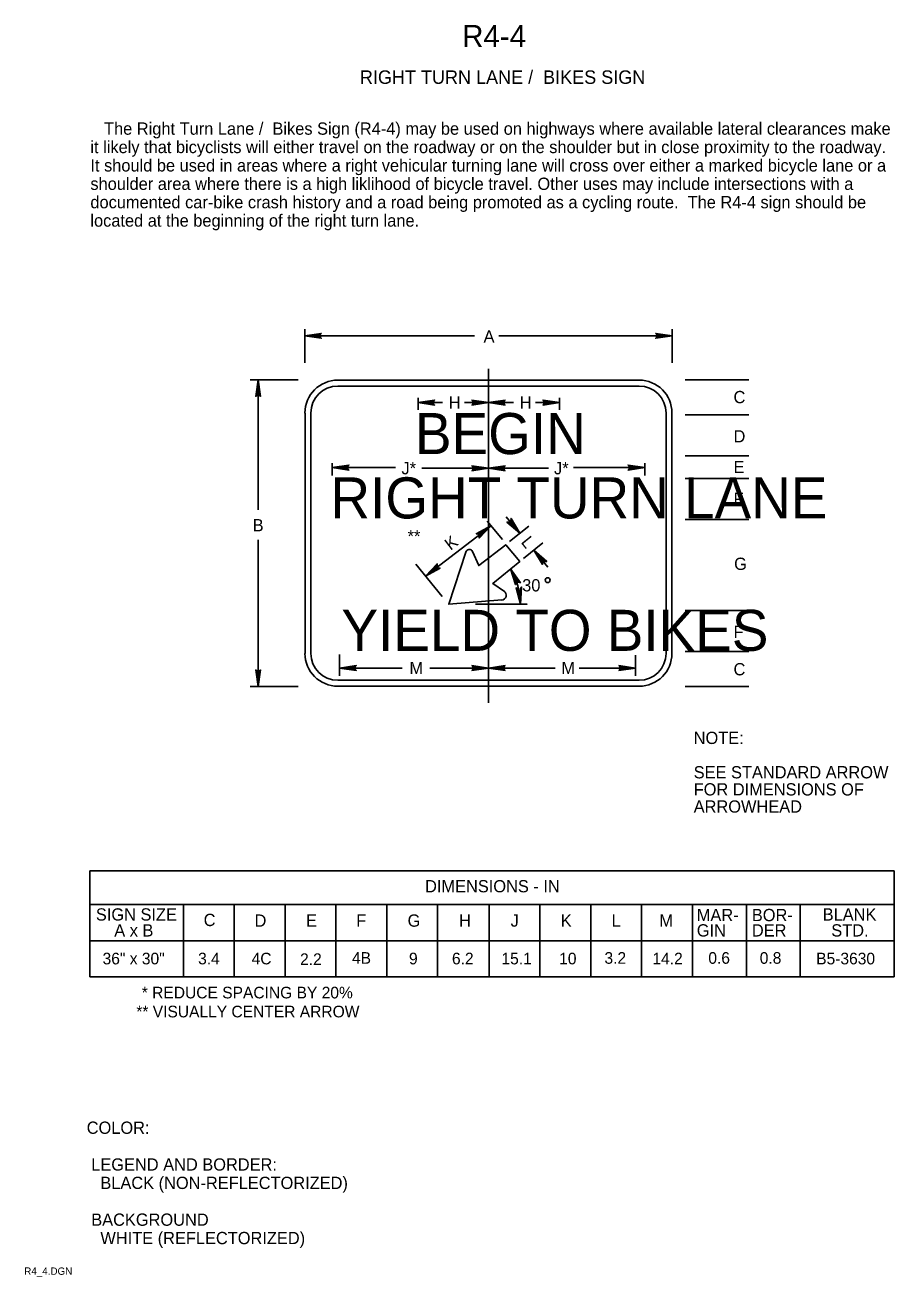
# Model space of a CAD drawing. Extents: x 0.013 to 0.19, y 0.004 to 0.259.
import ezdxf

# ---------------------------------------------------------------- set-up
doc = ezdxf.new("R2010")
doc.units = 0
for name, color, linetype in [('1', 7, 'Continuous'), ('2', 7, 'Continuous'), ('3', 7, 'Continuous'), ('7', 7, 'Continuous')]:
    doc.layers.add(name, color=color, linetype=linetype)

msp = doc.modelspace()

# ---------------------------------------------------------------- linework, layer by layer
at = {"layer": '1'}
for p, q in [((0.06963, 0.19038), (0.06963, 0.19725)), ((0.14463, 0.19038), (0.14463, 0.19725)), ((0.10425, 0.19587), (0.06963, 0.19587)), ((0.14463, 0.19587), (0.10925, 0.19587)), ((0.10712, 0.18913), (0.10712, 0.12102)), ((0.06825, 0.18688), (0.0585, 0.18688)), ((0.06012, 0.16037), (0.06012, 0.18688)), ((0.07637, 0.18682), (0.13787, 0.18682)), ((0.16025, 0.18688), (0.14725, 0.18688)), ((0.09275, 0.18075), (0.09275, 0.18325)), ((0.09775, 0.18225), (0.09275, 0.18225)), ((0.10712, 0.18225), (0.10225, 0.18225)), ((0.11225, 0.18225), (0.10712, 0.18225)), ((0.12162, 0.18225), (0.11675, 0.18225)), ((0.12162, 0.18075), (0.12162, 0.18325)), ((0.06968, 0.13112), (0.06968, 0.18013)), ((0.14457, 0.18013), (0.14457, 0.13112)), ((0.16025, 0.17975), (0.14725, 0.17975)), ((0.16025, 0.17137), (0.14725, 0.17137)), ((0.07525, 0.16737), (0.07525, 0.16987)), ((0.08812, 0.169), (0.07525, 0.169)), ((0.10712, 0.16887), (0.0935, 0.16887)), ((0.11938, 0.16887), (0.10712, 0.16887)), ((0.139, 0.169), (0.1245, 0.169)), ((0.139, 0.16737), (0.139, 0.16987)), ((0.16025, 0.16675), (0.14725, 0.16675)), ((0.11353, 0.15558), (0.11075, 0.15894)), ((0.16025, 0.15838), (0.14725, 0.15838)), ((0.09425, 0.14688), (0.10767, 0.15714)), ((0.10688, 0.15809), (0.11001, 0.15434)), ((0.11143, 0.15391), (0.11538, 0.15705)), ((0.06012, 0.12437), (0.06012, 0.15425)), ((0.11427, 0.15049), (0.11822, 0.15363)), ((0.11921, 0.14867), (0.11635, 0.15215)), ((0.09766, 0.1427), (0.09229, 0.14928)), ((0.115, 0.14113), (0.1045, 0.14113)), ((0.16025, 0.13987), (0.14725, 0.13987)), ((0.07675, 0.1265), (0.07675, 0.13087)), ((0.13712, 0.13075), (0.13712, 0.1265)), ((0.16025, 0.1315), (0.14725, 0.1315)), ((0.0895, 0.12812), (0.07675, 0.12812)), ((0.10712, 0.12812), (0.09513, 0.12812)), ((0.12075, 0.12812), (0.10712, 0.12812)), ((0.13712, 0.12812), (0.12563, 0.12812)), ((0.06825, 0.12437), (0.0585, 0.12437)), ((0.13787, 0.12443), (0.07637, 0.12443)), ((0.16025, 0.12437), (0.14725, 0.12437))]:
    msp.add_line(p, q, dxfattribs=at)
for points in [[(0.07287, 0.1955), (0.07275, 0.19575), (0.06963, 0.19587), (0.07287, 0.1955), (0.073, 0.19537), (0.06963, 0.19587), (0.07275, 0.196), (0.07287, 0.19625), (0.06963, 0.19587), (0.073, 0.19637), (0.07287, 0.19625)], [(0.14138, 0.19625), (0.1415, 0.196), (0.14463, 0.19587), (0.14138, 0.19625), (0.14125, 0.19637), (0.14463, 0.19587), (0.1415, 0.19575), (0.14138, 0.1955), (0.14463, 0.19587), (0.14125, 0.19537), (0.14138, 0.1955)], [(0.05975, 0.18363), (0.06, 0.18375), (0.06012, 0.18688), (0.05975, 0.18363), (0.05963, 0.1835), (0.06012, 0.18688), (0.06025, 0.18375), (0.0605, 0.18363), (0.06012, 0.18688), (0.06062, 0.1835), (0.0605, 0.18363)], [(0.096, 0.18188), (0.09588, 0.18213), (0.09275, 0.18225), (0.096, 0.18188), (0.09613, 0.18175), (0.09275, 0.18225), (0.09588, 0.18238), (0.096, 0.18263), (0.09275, 0.18225), (0.09613, 0.18275), (0.096, 0.18263)], [(0.10388, 0.18263), (0.104, 0.18238), (0.10712, 0.18225), (0.10388, 0.18263), (0.10375, 0.18275), (0.10712, 0.18225), (0.104, 0.18213), (0.10388, 0.18188), (0.10712, 0.18225), (0.10375, 0.18175), (0.10388, 0.18188)], [(0.11038, 0.18188), (0.11025, 0.18213), (0.10712, 0.18225), (0.11038, 0.18188), (0.1105, 0.18175), (0.10712, 0.18225), (0.11025, 0.18238), (0.11038, 0.18263), (0.10712, 0.18225), (0.1105, 0.18275), (0.11038, 0.18263)], [(0.11838, 0.18263), (0.1185, 0.18238), (0.12162, 0.18225), (0.11838, 0.18263), (0.11825, 0.18275), (0.12162, 0.18225), (0.1185, 0.18213), (0.11838, 0.18188), (0.12162, 0.18225), (0.11825, 0.18175), (0.11838, 0.18188)], [(0.0785, 0.16862), (0.07838, 0.16887), (0.07525, 0.169), (0.0785, 0.16862), (0.07863, 0.1685), (0.07525, 0.169), (0.07838, 0.16912), (0.0785, 0.16937), (0.07525, 0.169), (0.07863, 0.1695), (0.0785, 0.16937)], [(0.10388, 0.16925), (0.104, 0.169), (0.10712, 0.16887), (0.10388, 0.16925), (0.10375, 0.16937), (0.10712, 0.16887), (0.104, 0.16875), (0.10388, 0.1685), (0.10712, 0.16887), (0.10375, 0.16837), (0.10388, 0.1685)], [(0.11038, 0.1685), (0.11025, 0.16875), (0.10712, 0.16887), (0.11038, 0.1685), (0.1105, 0.16837), (0.10712, 0.16887), (0.11025, 0.169), (0.11038, 0.16925), (0.10712, 0.16887), (0.1105, 0.16937), (0.11038, 0.16925)], [(0.13575, 0.16937), (0.13587, 0.16912), (0.139, 0.169), (0.13575, 0.16937), (0.13562, 0.1695), (0.139, 0.169), (0.13587, 0.16887), (0.13575, 0.16862), (0.139, 0.169), (0.13562, 0.1685), (0.13575, 0.16862)], [(0.11175, 0.15838), (0.11163, 0.15825), (0.1135, 0.15563), (0.11175, 0.15838), (0.11175, 0.15863), (0.1135, 0.15563), (0.11138, 0.15788), (0.11113, 0.15788), (0.1135, 0.15563), (0.11088, 0.15788), (0.11113, 0.15788)], [(0.10487, 0.1555), (0.105, 0.15538), (0.10762, 0.15713), (0.10487, 0.1555), (0.10462, 0.1555), (0.10762, 0.15713), (0.10525, 0.15513), (0.10525, 0.15488), (0.10762, 0.15713), (0.10525, 0.15463), (0.10525, 0.15488)], [(0.11038, 0.14375), (0.108, 0.14538), (0.1135, 0.14988), (0.11063, 0.15325), (0.10512, 0.149), (0.10388, 0.15188), (0.10388, 0.15188)], [(0.1025, 0.15175), (0.099, 0.14113), (0.10988, 0.142)], [(0.11813, 0.1495), (0.11825, 0.14963), (0.11638, 0.15213), (0.11813, 0.1495), (0.11813, 0.14925), (0.11638, 0.15213), (0.1185, 0.14988), (0.11875, 0.14988), (0.11638, 0.15213), (0.119, 0.14988), (0.11875, 0.14988)], [(0.097, 0.1485), (0.09688, 0.14863), (0.09425, 0.14688), (0.097, 0.1485), (0.09725, 0.1485), (0.09425, 0.14688), (0.09663, 0.14888), (0.09663, 0.14913), (0.09425, 0.14688), (0.09663, 0.14938), (0.09663, 0.14913)], [(0.11275, 0.14538), (0.11288, 0.1455), (0.11163, 0.14838), (0.11275, 0.14538), (0.11263, 0.14513), (0.11163, 0.14838), (0.11313, 0.14563), (0.11338, 0.14563), (0.11163, 0.14838), (0.11363, 0.1455), (0.11338, 0.14563)], [(0.11375, 0.14438), (0.11363, 0.14438), (0.11363, 0.14113), (0.11375, 0.14438), (0.11388, 0.14463), (0.11363, 0.14113), (0.11313, 0.14413), (0.113, 0.14438), (0.11363, 0.14113), (0.11275, 0.1445), (0.113, 0.14438)], [(0.0605, 0.12763), (0.06025, 0.1275), (0.06012, 0.12437), (0.0605, 0.12763), (0.06062, 0.12775), (0.06012, 0.12437), (0.06, 0.1275), (0.05975, 0.12763), (0.06012, 0.12437), (0.05963, 0.12775), (0.05975, 0.12763)], [(0.08, 0.12775), (0.07988, 0.128), (0.07675, 0.12812), (0.08, 0.12775), (0.08013, 0.12763), (0.07675, 0.12812), (0.07988, 0.12825), (0.08, 0.1285), (0.07675, 0.12812), (0.08013, 0.12862), (0.08, 0.1285)], [(0.10388, 0.1285), (0.104, 0.12825), (0.10712, 0.12812), (0.10388, 0.1285), (0.10375, 0.12862), (0.10712, 0.12812), (0.104, 0.128), (0.10388, 0.12775), (0.10712, 0.12812), (0.10375, 0.12763), (0.10388, 0.12775)], [(0.11038, 0.12775), (0.11025, 0.128), (0.10712, 0.12812), (0.11038, 0.12775), (0.1105, 0.12763), (0.10712, 0.12812), (0.11025, 0.12825), (0.11038, 0.1285), (0.10712, 0.12812), (0.1105, 0.12862), (0.11038, 0.1285)], [(0.13387, 0.1285), (0.134, 0.12825), (0.13712, 0.12812), (0.13387, 0.1285), (0.13375, 0.12862), (0.13712, 0.12812), (0.134, 0.128), (0.13387, 0.12775), (0.13712, 0.12812), (0.13375, 0.12763), (0.13387, 0.12775)]]:
    msp.add_lwpolyline(points, dxfattribs=at)
msp.add_circle((0.11919, 0.14604), 0.0005, dxfattribs=at)
for centre, radius, start, end in [((0.07637, 0.18013), 0.0067, 90, 180), ((0.13787, 0.18013), 0.0067, 0, 90), ((0.10321, 0.15154), 0.000749, 26.7363, 165.3694), ((0.09907, 0.14104), 0.01455, 0.41, 30.1116), ((0.10975, 0.14299), 0.001, 274.205, 54.7468), ((0.07637, 0.13112), 0.0067, 180, 270), ((0.13787, 0.13112), 0.0067, 270, 0)]:
    msp.add_arc(centre, radius, start, end, dxfattribs=at)
msp.add_ellipse((0.09898, 0.14108), major_axis=(0, -0.0161), ratio=0.99998, start_param=1.5707963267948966, end_param=1.5707963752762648, dxfattribs=at)
at = {"layer": '3'}
for p, q in [((0.07637, 0.18563), (0.13787, 0.18563)), ((0.07088, 0.13112), (0.07088, 0.18013)), ((0.14338, 0.18013), (0.14338, 0.13112)), ((0.13787, 0.12563), (0.07637, 0.12563)), ((0.02575, 0.08675), (0.18988, 0.08675)), ((0.02575, 0.08675), (0.02575, 0.06513)), ((0.18988, 0.08675), (0.18988, 0.06513)), ((0.18988, 0.07988), (0.02575, 0.07988)), ((0.04487, 0.07988), (0.04487, 0.06513)), ((0.05525, 0.07988), (0.05525, 0.06513)), ((0.06563, 0.07988), (0.06563, 0.06513)), ((0.076, 0.07988), (0.076, 0.06513)), ((0.08638, 0.07988), (0.08638, 0.06513)), ((0.09675, 0.07988), (0.09675, 0.06513)), ((0.10725, 0.07988), (0.10725, 0.06513)), ((0.11763, 0.07988), (0.11763, 0.06513)), ((0.128, 0.07988), (0.128, 0.06513)), ((0.13837, 0.07988), (0.13837, 0.06513)), ((0.14875, 0.07988), (0.14875, 0.06513)), ((0.15975, 0.07988), (0.15975, 0.06513)), ((0.17075, 0.07988), (0.17075, 0.06513)), ((0.18988, 0.0725), (0.02575, 0.0725)), ((0.18988, 0.06513), (0.02575, 0.06513))]:
    msp.add_line(p, q, dxfattribs=at)
for centre, start, end in [((0.07637, 0.18013), 90, 180), ((0.13787, 0.18013), 0, 90), ((0.07637, 0.13112), 180, 270), ((0.13787, 0.13112), 270, 0)]:
    msp.add_arc(centre, 0.0055, start, end, dxfattribs=at)

# ---------------------------------------------------------------- texts
at = {"layer": '1'}
for s, height, p in [('R4-4', 0.0045, (0.10175, 0.25475)), ('RIGHT TURN LANE /  BIKES SIGN', 0.0027503, (0.08088, 0.24725)), ('A', 0.0025, (0.10612, 0.1945)), ('C', 0.0025, (0.15713, 0.18213)), ('H', 0.0025, (0.099, 0.181)), ('H', 0.0025, (0.1135, 0.181)), ('BEGIN', 0.008375, (0.09212, 0.17175)), ('D', 0.0025, (0.15713, 0.17413)), ('J*', 0.0025, (0.08937, 0.16762)), ('J*', 0.0025, (0.1205, 0.16762)), ('E', 0.0025, (0.15713, 0.16787)), ('RIGHT TURN LANE', 0.0083752, (0.07487, 0.15863)), ('F', 0.0025, (0.15713, 0.16137)), ('B', 0.0025, (0.059, 0.156)), ('**', 0.0025, (0.09062, 0.15375)), ('G', 0.0025, (0.15725, 0.14813)), ('30', 0.0025, (0.114, 0.14375)), ('YIELD TO BIKES', 0.0083752, (0.07712, 0.13162)), ('F', 0.0025, (0.15713, 0.13425)), ('M', 0.0025, (0.091, 0.12688)), ('M', 0.0025, (0.122, 0.12688)), ('C', 0.0025, (0.15713, 0.12663)), ('NOTE:', 0.0025, (0.149, 0.11263)), ('SEE STANDARD ARROW', 0.0024998, (0.149, 0.10562)), ('FOR DIMENSIONS OF', 0.0024998, (0.149, 0.10213)), ('ARROWHEAD', 0.0025, (0.149, 0.09863)), ('R4_4.DGN', 0.0015, (0.01238, 0.00438))]:
    msp.add_text(s, height=height, dxfattribs=at).set_placement(p)
for s, rotation, p in [('K', 37.4215, (0.09938, 0.152)), ('L', 308.9837, (0.11363, 0.15375))]:
    msp.add_text(s, height=0.0025, rotation=rotation, dxfattribs=at).set_placement(p)
at = {"layer": '2'}
msp.add_text('DIMENSIONS - IN', height=0.0024998, dxfattribs=at).set_placement((0.09418, 0.08238))
at = {"layer": '3'}
for s, height, p in [('SIGN SIZE', 0.0025, (0.027, 0.07662)), ('C', 0.0025, (0.049, 0.0755)), ('D', 0.0025, (0.05938, 0.07537)), ('E', 0.0025, (0.06988, 0.07537)), ('F', 0.0025, (0.08013, 0.07537)), ('G', 0.0025, (0.09062, 0.07537)), ('H', 0.0025, (0.10113, 0.07537)), ('J', 0.0025, (0.11163, 0.07537)), ('K', 0.0025, (0.12187, 0.07537)), ('L', 0.0025, (0.13225, 0.07537)), ('M', 0.0025, (0.142, 0.07537)), ('MAR-', 0.0025, (0.14963, 0.0765)), ('BOR-', 0.0025, (0.16087, 0.0765)), ('BLANK', 0.0025, (0.17533, 0.07662)), ('A x B', 0.0025, (0.03075, 0.07337)), ('GIN', 0.0025, (0.14963, 0.07337)), ('DER', 0.0025, (0.16087, 0.07337)), ('STD.', 0.0025, (0.17708, 0.07337)), ('36" x 30"', 0.002375, (0.02837, 0.06769)), ('3.4', 0.002375, (0.04786, 0.06769)), ('4C', 0.002375, (0.05879, 0.06769)), ('2.2', 0.002375, (0.06867, 0.06756)), ('4B', 0.002375, (0.07927, 0.06781)), ('9', 0.00238, (0.0909, 0.06769)), ('6.2', 0.002375, (0.09967, 0.06769)), ('15.1', 0.002375, (0.10977, 0.06769)), ('10', 0.002375, (0.12155, 0.06769)), ('3.2', 0.002375, (0.13079, 0.06781)), ('14.2', 0.002375, (0.14058, 0.06769)), ('0.6', 0.002375, (0.15199, 0.06781)), ('0.8', 0.002375, (0.16248, 0.06781)), ('B5-3630', 0.002375, (0.174, 0.06769)), ('* REDUCE SPACING BY 20%', 0.0023752, (0.03637, 0.06075)), ('** VISUALLY CENTER ARROW', 0.0023752, (0.03525, 0.05688))]:
    msp.add_text(s, height=height, dxfattribs=at).set_placement(p)
at = {"layer": '7'}
for s, height, p in [('   The Right Turn Lane /  Bikes Sign (R4-4) may be used on highways where available lateral clearances make', 0.00249975, (0.02588, 0.23688)), ('it likely that bicyclists will either travel on the roadway or on the shoulder but in close proximity to the roadway.', 0.00249975, (0.02588, 0.23313)), ('It should be used in areas where a right vehicular turning lane will cross over either a marked bicycle lane or a', 0.00249975, (0.02588, 0.22938)), ('shoulder area where there is a high liklihood of bicycle travel. Other uses may include intersections with a', 0.00249975, (0.02588, 0.22563)), ('documented car-bike crash history and a road being promoted as a cycling route.  The R4-4 sign should be', 0.00249975, (0.02588, 0.22188)), ('located at the beginning of the right turn lane.', 0.0024998, (0.02588, 0.21813)), ('COLOR:', 0.0025, (0.02513, 0.03313)), (' LEGEND AND BORDER:', 0.0024998, (0.02513, 0.02563)), ('   BLACK (NON-REFLECTORIZED)', 0.0024998, (0.02513, 0.02188)), (' BACKGROUND', 0.0024998, (0.02513, 0.01438)), ('   WHITE (REFLECTORIZED)', 0.0024998, (0.02513, 0.01063))]:
    msp.add_text(s, height=height, dxfattribs=at).set_placement(p)

doc.saveas('drawing.dxf')
